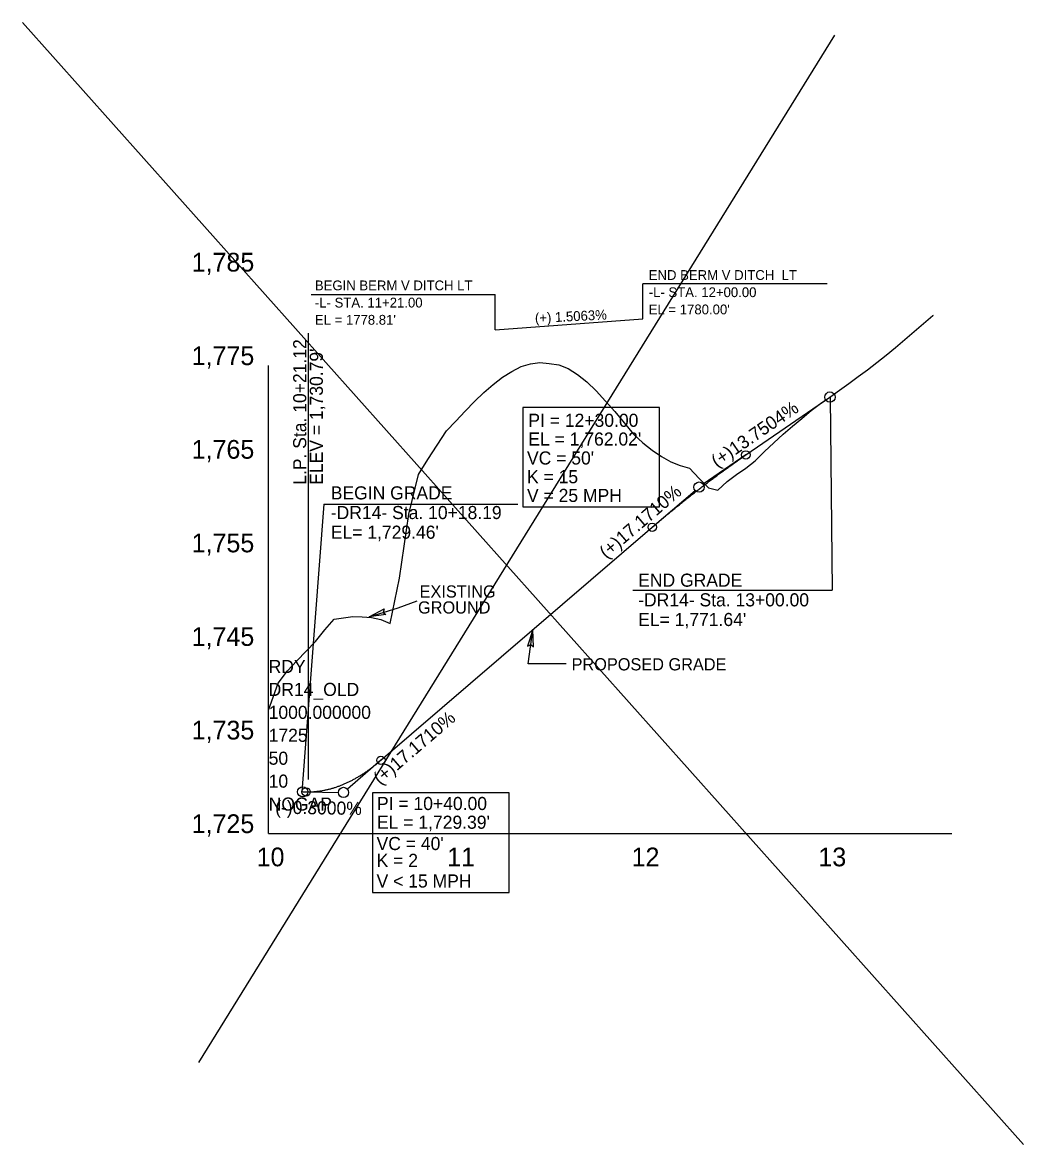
# Model space of a CAD drawing. Extents: x 498575 to 532350, y 405181 to 484585.
# Drawn here: x 528174 to 528709, y 452177 to 452777 of the extents above; entities that cross this region are included whole.
import ezdxf

# ---------------------------------------------------------------- set-up
doc = ezdxf.new("R2010")
doc.units = 0
for name, color, linetype in [('Exist Profile Cell', 7, 'Continuous'), ('Exist Vertical Profile Ground Line', 7, 'Continuous'), ('Exist Vertical Profile Horizontal Axis Label Major', 7, 'Continuous'), ('Exist Vertical Profile Vertical Axis Label', 7, 'Continuous'), ('Prop Grid Mask', 7, 'Continuous'), ('Prop PFL Text', 7, 'Continuous'), ('Prop Vertical Profile Curve Label', 7, 'Continuous'), ('Prop Vertical Profile Ditch Grade Left', 7, 'Continuous'), ('Prop Vertical Profile Ditch Grade Left Label', 7, 'Continuous'), ('Prop Vertical Profile Grade', 7, 'Continuous'), ('Prop Vertical Profile Grade Label', 7, 'Continuous'), ('Prop Vertical Profile Strip Grade', 7, 'Continuous'), ('Prop VPI Label', 7, 'Continuous'), ('Scratch_Level_5', 7, 'Continuous')]:
    doc.layers.add(name, color=color, linetype=linetype)

msp = doc.modelspace()

# ---------------------------------------------------------------- linework, layer by layer
at = {"layer": 'Exist Profile Cell'}
for q in [(528305.25, 452593.43), (528670.37, 452343.43), (528305.25, 452343.43)]:
    msp.add_line((528305.25, 452343.43), q, dxfattribs=at)
at = {"layer": 'Exist Vertical Profile Ground Line'}
msp.add_lwpolyline([(528305.25, 452409.29), (528310.25, 452423.83), (528315.25, 452430.3), (528320.25, 452435.71), (528325.25, 452440.84), (528330.25, 452445.97), (528335.25, 452452.18), (528340.25, 452457.98), (528345.25, 452458.6), (528350.25, 452459.33), (528355.25, 452459.28), (528360.25, 452458.85), (528365.25, 452457.83), (528370.25, 452455.7), (528375.25, 452479.82), (528380.25, 452514.12), (528385.25, 452535.23), (528390.25, 452543.27), (528395.25, 452550.98), (528400.25, 452558.54), (528405.25, 452563.83), (528410.25, 452569.09), (528415.25, 452574.25), (528420.25, 452579.07), (528425.25, 452583.32), (528430.25, 452587.22), (528435.25, 452590.25), (528440.25, 452592.89), (528445.25, 452594.33), (528450.25, 452595.03), (528455.25, 452594.62), (528460.25, 452593.84), (528465.25, 452591.96), (528470.25, 452588.71), (528475.25, 452584.71), (528480.25, 452579.93), (528485.25, 452574.44), (528490.25, 452568.88), (528495.25, 452562.89), (528500.25, 452556.74), (528505.25, 452552.15), (528510.25, 452548.22), (528515.25, 452544.89), (528520.25, 452542.07), (528525.25, 452540.05), (528530.25, 452538.65), (528535.25, 452533.1), (528540.25, 452528.13), (528545.25, 452526.91), (528550.25, 452531.47), (528555.25, 452535.27), (528560.25, 452538.63), (528565.25, 452542.62), (528570.25, 452547.49), (528575.25, 452552.12), (528580.25, 452556.77), (528585.25, 452561.15), (528590.25, 452565.23), (528595.25, 452569.41), (528600.25, 452573.17), (528605.25, 452576.63), (528610.25, 452580.34), (528615.25, 452583.95), (528620.25, 452587.53), (528625.25, 452591.1), (528630.25, 452595.01), (528635.25, 452599.02), (528640.25, 452603.09), (528645.25, 452607.4), (528650.25, 452611.72), (528655.25, 452615.97), (528660.25, 452620.19), (528660.54, 452620.43)], dxfattribs=at)
at = {"layer": 'Prop Grid Mask'}
for points in [[(528441.12, 452517.98), (528514.13, 452517.98), (528514.13, 452571.08), (528441.12, 452571.08)], [(528360.74, 452311.99), (528433.75, 452311.99), (528433.75, 452365.09), (528360.74, 452365.09)]]:
    msp.add_lwpolyline(points, close=True, dxfattribs=at)
at = {"layer": 'Prop PFL Text'}
for p, q in [((528358.91, 452459.16), (528374.48, 452464.01)), ((528374.48, 452464.01), (528384.58, 452467.77)), ((528443.88, 452434.01), (528446.42, 452452.24)), ((528464.25, 452434.01), (528443.88, 452434.01))]:
    msp.add_line(p, q, dxfattribs=at)
for points in [[(528367.96, 452460.42), (528358.91, 452459.16), (528367.04, 452463.44), (528366.44, 452461.56)], [(528446.71, 452443.11), (528446.42, 452452.24), (528443.58, 452443.5), (528445.33, 452444.42)]]:
    msp.add_lwpolyline(points, close=True, dxfattribs=at)
at = {"layer": 'Prop Vertical Profile Curve Label'}
for centre in [(528560.25, 452545.69), (528510.25, 452507.04), (528365.25, 452382.55), (528325.25, 452365.68)]:
    msp.add_circle(centre, 2.25, dxfattribs=at)
at = {"layer": 'Prop Vertical Profile Ditch Grade Left'}
msp.add_lwpolyline([(528426.25, 452612.48), (528505.25, 452618.43)], dxfattribs=at)
at = {"layer": 'Prop Vertical Profile Ditch Grade Left Label'}
for p, q in [((528505.25, 452618.43), (528505.25, 452637.07)), ((528603.73, 452637.07), (528505.25, 452637.07)), ((528327.99, 452631.48), (528426.25, 452631.48)), ((528426.25, 452612.48), (528426.25, 452631.48))]:
    msp.add_line(p, q, dxfattribs=at)
at = {"layer": 'Prop Vertical Profile Grade'}
for p, q in [((528560.25, 452545.69), (528605.25, 452576.63)), ((528365.25, 452382.55), (528510.25, 452507.04)), ((528323.43, 452365.71), (528325.25, 452365.68))]:
    msp.add_line(p, q, dxfattribs=at)
for points in [[(528510.25, 452507.04), (528511.25, 452507.9), (528512.25, 452508.75), (528513.25, 452509.6), (528514.25, 452510.45), (528515.25, 452511.29), (528516.25, 452512.13), (528517.25, 452512.97), (528518.25, 452513.8), (528519.25, 452514.63), (528520.25, 452515.46), (528521.25, 452516.28), (528522.25, 452517.1), (528523.25, 452517.91), (528524.25, 452518.73), (528525.25, 452519.53), (528526.25, 452520.34), (528527.25, 452521.14), (528528.25, 452521.94), (528529.25, 452522.74), (528530.25, 452523.53), (528531.25, 452524.32), (528532.25, 452525.1), (528533.25, 452525.88), (528534.25, 452526.66), (528535.25, 452527.44), (528536.25, 452528.21), (528537.25, 452528.97), (528538.25, 452529.74), (528539.25, 452530.5), (528540.25, 452531.26), (528541.25, 452532.01), (528542.25, 452532.76), (528543.25, 452533.51), (528544.25, 452534.25), (528545.25, 452534.99), (528546.25, 452535.73), (528547.25, 452536.47), (528548.25, 452537.2), (528549.25, 452537.92), (528550.25, 452538.65), (528551.25, 452539.37), (528552.25, 452540.08), (528553.25, 452540.8), (528554.25, 452541.51), (528555.25, 452542.21), (528556.25, 452542.92), (528557.25, 452543.61), (528558.25, 452544.31), (528559.25, 452545), (528560.25, 452545.69)], [(528325.25, 452365.68), (528326.05, 452365.67), (528326.85, 452365.68), (528327.65, 452365.71), (528328.45, 452365.74), (528329.25, 452365.79), (528330.05, 452365.86), (528330.85, 452365.94), (528331.65, 452366.03), (528332.45, 452366.14), (528333.25, 452366.26), (528334.05, 452366.39), (528334.85, 452366.54), (528335.65, 452366.7), (528336.45, 452366.88), (528337.25, 452367.07), (528338.05, 452367.28), (528338.85, 452367.5), (528339.65, 452367.73), (528340.45, 452367.97), (528341.25, 452368.24), (528342.05, 452368.51), (528342.85, 452368.8), (528343.65, 452369.1), (528344.45, 452369.42), (528345.25, 452369.75), (528346.05, 452370.09), (528346.85, 452370.45), (528347.65, 452370.82), (528348.45, 452371.21), (528349.25, 452371.61), (528350.05, 452372.02), (528350.85, 452372.45), (528351.65, 452372.89), (528352.45, 452373.35), (528353.25, 452373.82), (528354.05, 452374.3), (528354.85, 452374.8), (528355.65, 452375.31), (528356.45, 452375.84), (528357.25, 452376.38), (528358.05, 452376.94), (528358.85, 452377.5), (528359.65, 452378.09), (528360.45, 452378.68), (528361.25, 452379.29), (528362.05, 452379.92), (528362.85, 452380.55), (528363.65, 452381.21), (528364.45, 452381.87), (528365.25, 452382.55)]]:
    msp.add_spline(points, degree=3, dxfattribs=at)
at = {"layer": 'Prop Vertical Profile Strip Grade'}
msp.add_line((528326.37, 452610.7), (528326.37, 452372.36), dxfattribs=at)
at = {"layer": 'Prop VPI Label'}
for p, q in [((528605.27, 452576.65), (528606.43, 452473.43)), ((528560.25, 452545.69), (528537.52, 452530.06)), ((528510.25, 452507.04), (528533.16, 452526.71)), ((528334.79, 452519.41), (528323, 452365.71)), ((528334.79, 452519.41), (528438.34, 452519.41)), ((528499.87, 452473.43), (528606.43, 452473.43)), ((528365.25, 452382.55), (528347.34, 452367.17)), ((528325.25, 452365.68), (528342.5, 452365.42))]:
    msp.add_line(p, q, dxfattribs=at)
for centre in [(528605.25, 452576.63), (528535.25, 452528.5), (528323.43, 452365.71), (528345.25, 452365.38)]:
    msp.add_circle(centre, 2.75, dxfattribs=at)
at = {"layer": 'Scratch_Level_5'}
for p, q in [((528173.66, 452776.77), (528708.7, 452177.27)), ((528267.88, 452221.05), (528607.75, 452770.03))]:
    msp.add_line(p, q, dxfattribs=at)

# ---------------------------------------------------------------- texts
at = {"layer": 'Exist Profile Cell'}
for s, p in [('RDY', (528305.25, 452429.18)), ('DR14_OLD', (528305.25, 452416.93)), ('1000.000000', (528305.25, 452404.68)), ('1725', (528305.25, 452392.43)), ('50', (528305.25, 452380.18)), ('10', (528305.25, 452367.93)), ('NOGAP', (528305.25, 452355.68))]:
    msp.add_text(s, height=7, dxfattribs=at).set_placement(p)
at = {"layer": 'Exist Vertical Profile Horizontal Axis Label Major'}
for s, p in [('10', (528298.83, 452325.93)), ('11', (528400.67, 452325.93)), ('12', (528499.22, 452325.93)), ('13', (528599.06, 452325.93))]:
    msp.add_text(s, height=10, dxfattribs=at).set_placement(p)
at = {"layer": 'Exist Vertical Profile Vertical Axis Label'}
for s, p in [('1,785', (528264.1, 452643.68)), ('1,775', (528264.1, 452593.68)), ('1,765', (528264.1, 452543.68)), ('1,755', (528264.1, 452493.68)), ('1,745', (528264.1, 452443.68)), ('1,735', (528264.1, 452393.68)), ('1,725', (528264.1, 452343.68))]:
    msp.add_text(s, height=10, dxfattribs=at).set_placement(p)
at = {"layer": 'Prop PFL Text'}
for s, height, p in [('EXISTING ', 6.516, (528385.92, 452469.5)), ('GROUND', 6.516, (528385.07, 452460.96)), ('PROPOSED GRADE', 6.5157, (528467.13, 452430.59))]:
    msp.add_text(s, height=height, dxfattribs=at).set_placement(p)
at = {"layer": 'Prop Vertical Profile Curve Label'}
for s, p in [('V = 25 MPH ', (528443.31, 452520.58)), ("VC = 40'", (528362.93, 452334.59)), ('K = 2', (528362.93, 452325.59)), ('V < 15 MPH ', (528362.93, 452314.59))]:
    msp.add_text(s, height=7, dxfattribs=at).set_placement(p)
at = {"layer": 'Prop Vertical Profile Ditch Grade Left Label'}
for s, rotation, p in [('END BERM V DITCH  LT', 360, (528508.38, 452639.2)), ('BEGIN BERM V DITCH LT', 360, (528329.95, 452633.65)), ('-L- STA. 12+00.00', 360, (528508.38, 452630.01)), ('-L- STA. 11+21.00', 360, (528329.95, 452624.46)), ("EL = 1780.00'", 360, (528508.38, 452620.82)), ("EL = 1778.81'", 360, (528329.95, 452615.27)), ('(+) 1.5063%', 2.82359, (528447.69, 452616.18))]:
    msp.add_text(s, height=5.25, rotation=rotation, dxfattribs=at).set_placement(p)
at = {"layer": 'Prop Vertical Profile Grade Label'}
for s, rotation, p in [('(+)13.7504%', 34.50937, (528544.81, 452538.71)), ('(+)17.1710%', 40.64779, (528485.72, 452489.93)), ('(+)17.1710%', 40.64779, (528364.89, 452369.06)), ('(-)0.3000%', 359.14055, (528308.69, 452354.03))]:
    msp.add_text(s, height=7, rotation=rotation, dxfattribs=at).set_placement(p)
at = {"layer": 'Prop Vertical Profile Strip Grade'}
for s, p in [('L.P. Sta. 10+21.12', (528325.35, 452529.73)), ("ELEV = 1,730.79'", (528334.22, 452529.73))]:
    msp.add_text(s, height=7, rotation=90, dxfattribs=at).set_placement(p)
at = {"layer": 'Prop VPI Label'}
for s, p in [('PI = 12+30.00', (528444.03, 452560.71)), ("EL = 1,762.02'", (528444.03, 452550.71)), ("VC = 50'", (528443.31, 452540.58)), ('K = 15', (528443.31, 452530.58)), ('BEGIN GRADE', (528338.45, 452521.93)), ('-DR14- Sta. 10+18.19', (528338.45, 452511.43)), ("EL= 1,729.46'", (528338.45, 452500.93)), ('END GRADE', (528502.74, 452475.29)), ('-DR14- Sta. 13+00.00', (528502.74, 452464.79)), ("EL= 1,771.64'", (528502.74, 452454.29)), ('PI = 10+40.00', (528363.14, 452355.98)), ("EL = 1,729.39'", (528363.14, 452345.98))]:
    msp.add_text(s, height=7, dxfattribs=at).set_placement(p)

doc.saveas('drawing.dxf')
